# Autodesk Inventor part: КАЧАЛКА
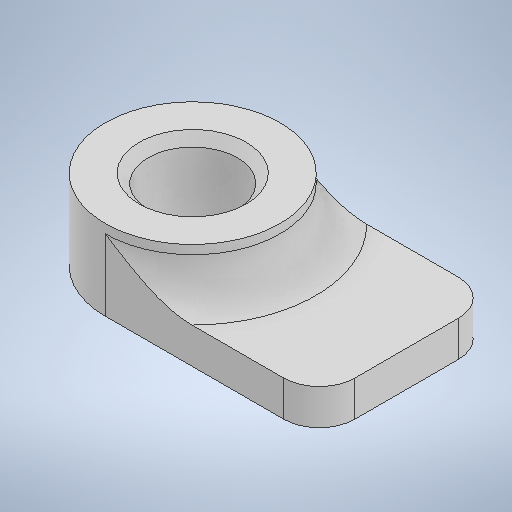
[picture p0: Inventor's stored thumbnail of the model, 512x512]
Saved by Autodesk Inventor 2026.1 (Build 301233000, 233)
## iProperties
Created: 2026-01
Part Number: КАЧАЛКА
Material: Типовые
Document SubType Name: Modeling
Designer: Yury Melnikov
Density: 1 g/cm^3
Appearance: По умолчанию
Author: Yury Melnikov
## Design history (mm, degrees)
sketch "Эскиз1"
  geometry: L1 (0, 4.9)-(-10, 4.9); L2 (-12, 2.9)-(-12, -2.9); L3 (-10, -4.9)-(0, -4.9); L4 (0, -4.9)-(0, 4.9); C1 r 2.5 at (0, 0); A1 r 4.9 centre (0, 0) between (0, -4.9) and (0, 4.9); A2 r 2 centre (-10, 2.9) between (-10, 4.9) and (-12, 2.9); A3 r 2 centre (-10, -2.9) between (-12, -2.9) and (-10, -4.9); 2 further points
  constraints: 8 end point, 6 point on circle, 4 centre point, 4 tangent, 2 parallel, 2 point on line, 1 coincident, 1 equal radius, 1 horizontal, 1 midpoint, 1 perpendicular
  dimensions: "d0" = 5 diameter of C1; "d1" = 2.4 radial gap between concentric circles of C1 A1; "d2" = 12 distance of point (-12, -4.9) L3.end; "d3" = 2 radius of A2 (derived)
extrude "Выдавливание1" new body sketch "Эскиз1" distance "d4" = 2; taper "d5" = 0 deg
sketch "Эскиз2"
  geometry: C1 r 4.9 at (0, 0); C2 r 2.5 at (0, 0) reference; A1 r 4.9 centre (0, 0) between (0, 4.9) and (0, -4.9) reference; 1 further point
  constraints: 2 concentric, 1 centre point
extrude "Выдавливание2" join sketch "Эскиз2" distance "d6" = 2.5; taper "d7" = 0 deg
chamfer "Фаска1" distance "d8" = 0.5; stored, may be unused: second distance "d9" = 2, angle "d10" = 45 deg
fillet "Сопряжение1" dims "d11" = 2
node "Твердое тело1"
